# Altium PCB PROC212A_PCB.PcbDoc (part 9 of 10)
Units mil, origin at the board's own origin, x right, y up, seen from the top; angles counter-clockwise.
Board outline 3032.48 x 3598.78 mil, 4 copper layers (Top Layer, L2_GND1, L3_PWR1, Bottom Layer), stack 60.58 mil thick; 432 components, 310 nets, 7775 pads, 1236 vias.
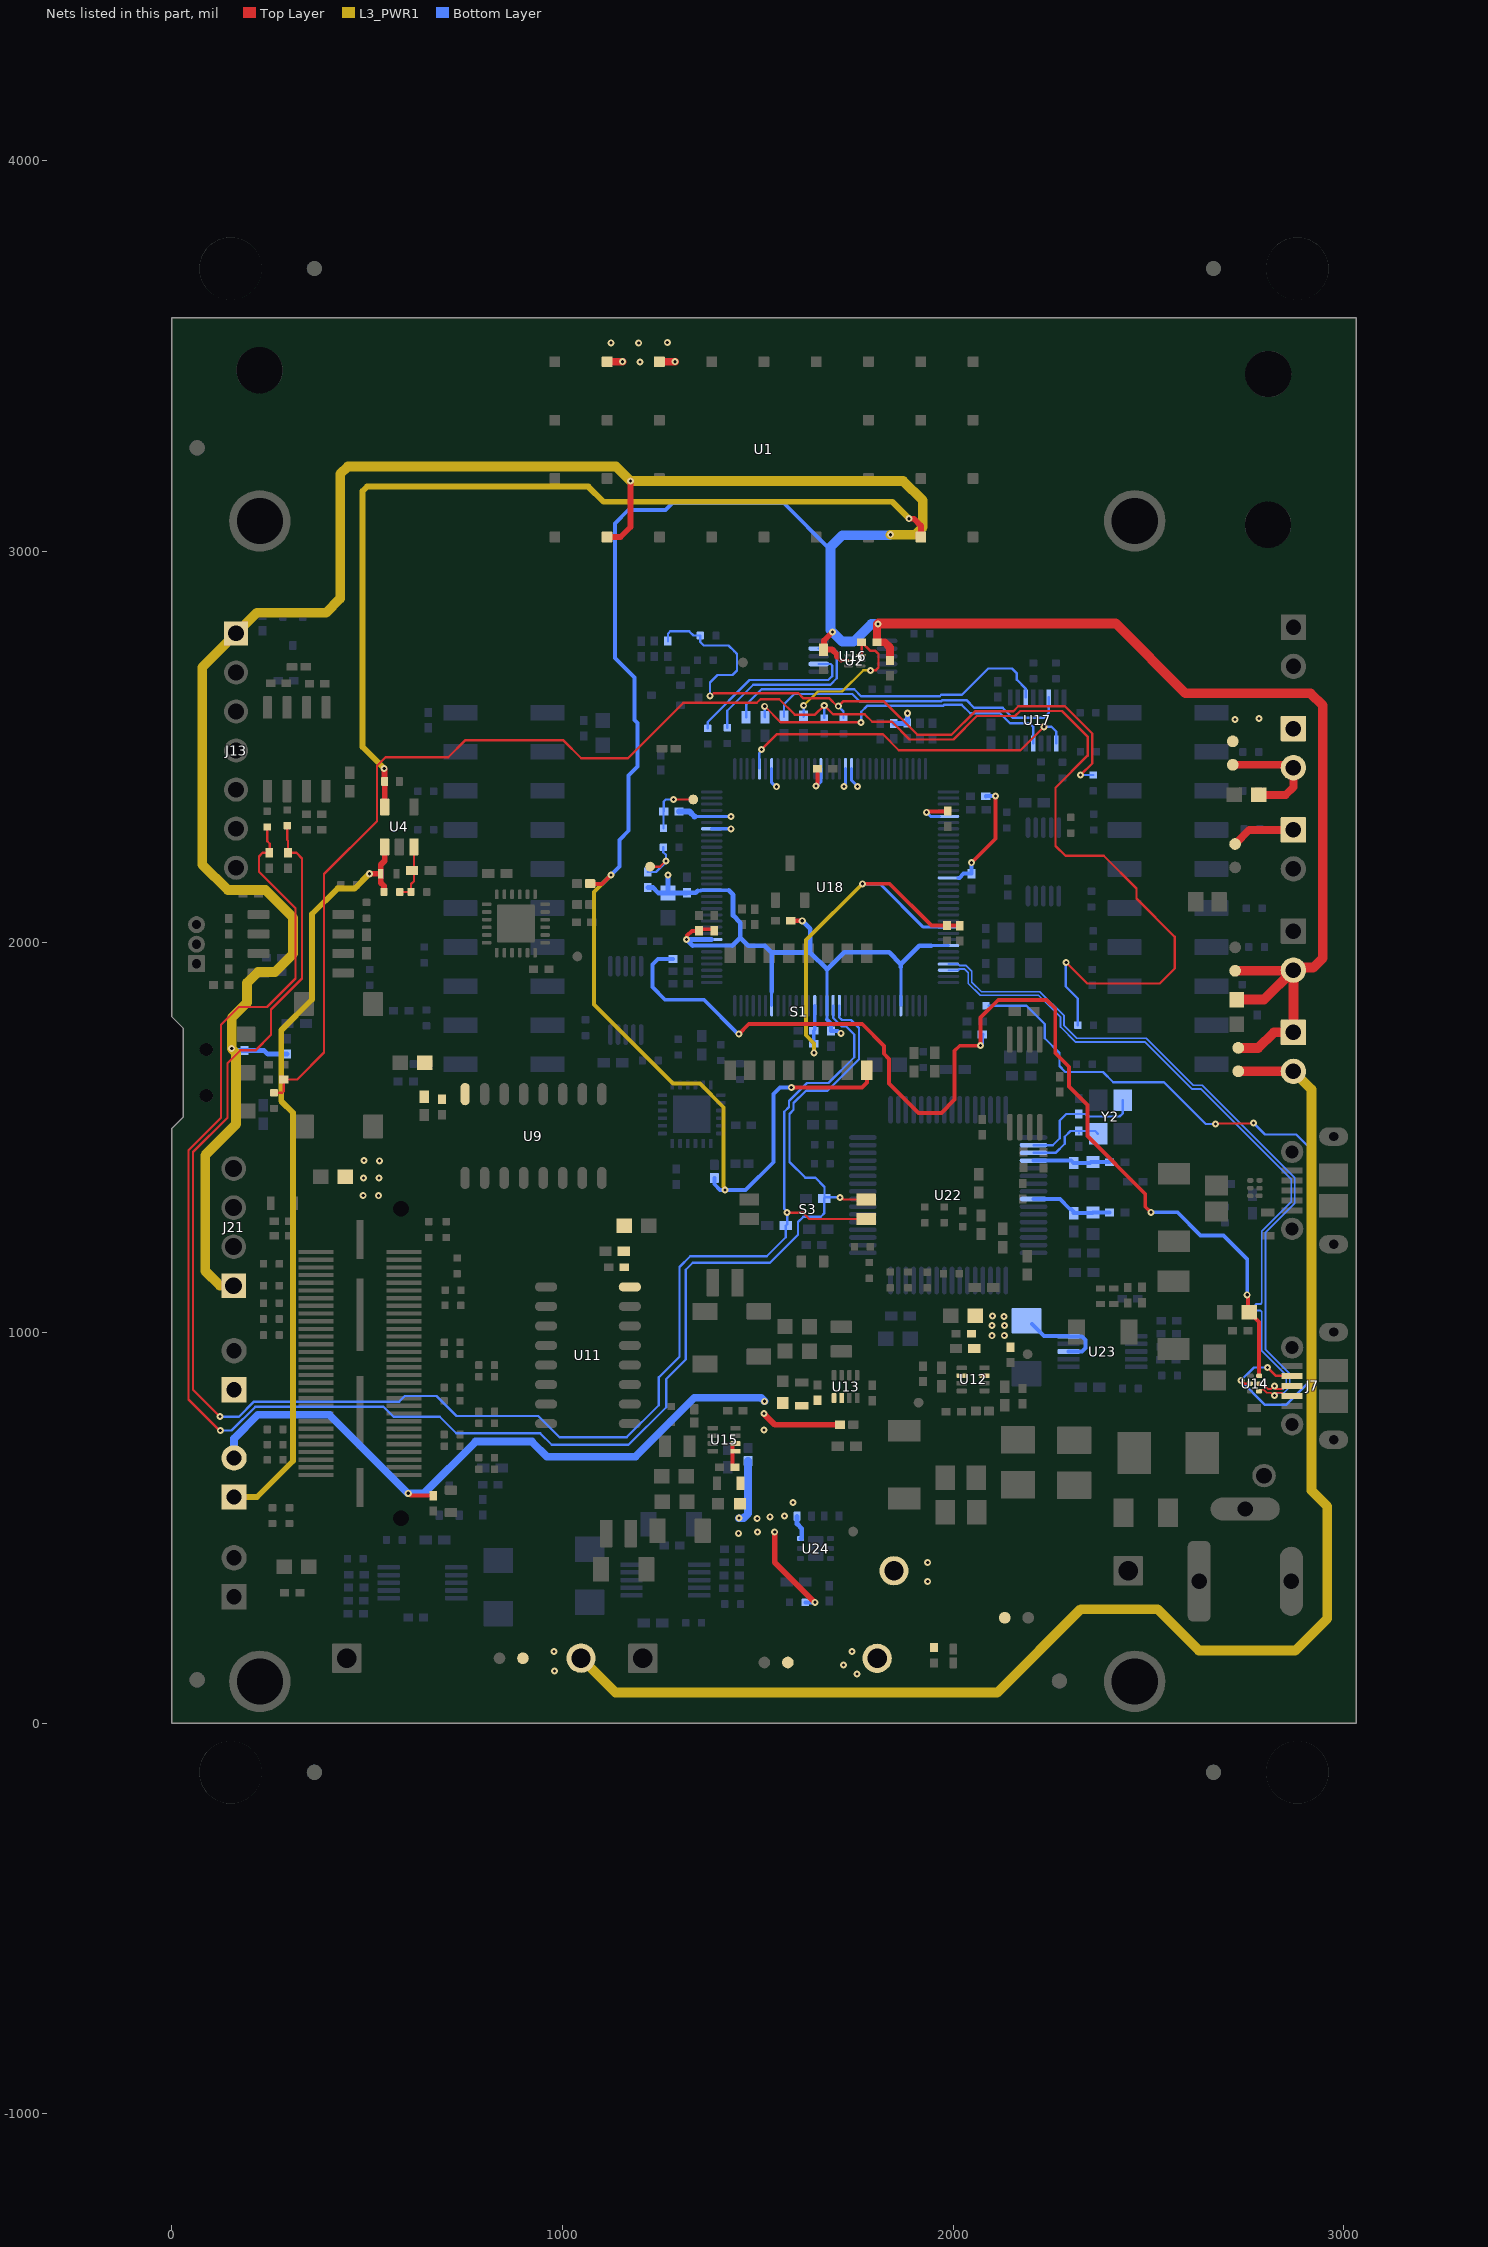
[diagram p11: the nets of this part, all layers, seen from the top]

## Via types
v1: diameter 18, hole 8, Top Layer to Bottom Layer, tented both sides, 1224 vias
v2: diameter 19.68, hole 7.87, Top Layer to Bottom Layer, tented both sides, 10 vias
v3: diameter 19.68, hole 7.87, Top Layer to Bottom Layer, 2 vias

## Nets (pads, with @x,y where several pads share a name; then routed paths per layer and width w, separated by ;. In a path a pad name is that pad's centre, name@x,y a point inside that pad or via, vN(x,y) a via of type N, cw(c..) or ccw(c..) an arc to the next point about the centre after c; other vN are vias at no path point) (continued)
VCC_5V: C42.1 C44.1 C45.1 C50.1 C52.1 C54.1 C93.2 J9.2 J23.2 R79.1 R88.2 R91.2 R93.2 R200.1 R217.2 U13.1 U13.2 U15.1 U15.2 U24.6 | length 2455.6
  Top Layer w10: v1(605.04,588.74) 611.23,582.55 R88.2@668.94,582.55 ; C50.1@1434.81,661.43 U15.2@1434.81,715.37 ; U15.2@1442.31,715.37 U15.2@1443.1,716.16
  Top Layer w15: v1(1515.53,792.55) 1543.71,764.37 R79.1@1710.91,764.37 ; v1(1543.33,489.54) 1543.33,411.62 1645.36,309.6 v1(1646.03,309.6)
  Bottom Layer w10: R217.2@1621.39,309.52 1645.96,309.52 v1(1646.03,309.6)
  Bottom Layer w12: C93.2@1600.57,530.16 1600.57,510.15 1612.31,498.42 1612.31,473.03 1612.21,472.94 U24.6@1609.67,472.94
  Bottom Layer w20: J23.2@158.99,679.14 158.99,728.69 219.9,789.61 403.11,789.61 v1@603.98,588.74 ; v1@605.23,588.92 645.39,588.92 777.56,721.09 921.53,721.09 960.12,682.5 1186.49,682.5 1337.42,833.43 1508.41,833.43 v1(1517.53,824.31) ; v1(1451.96,525.03) 1463.6,525.03 1475.32,536.74 R200.1@1475.31,671.1
  other v1: 1935.1,362.4 1935.1,411.4 1450.85,486.29 1499.07,489.63 1498.51,523.91 1531.17,528.58 1567.91,530.32 1589.93,564.89 1515.93,750.88
VCC_5V_IN: C34.1 C38.1 C39.1 J22.1 R37.1 R65.2 R192.1 U12.2 U12.7 U23.8 U23.10 | length 221.8
  Bottom Layer w10: R192.1@2202.24,1021.97 2233.16,991.04 U23.10@2295.6,991.04 2296.15,990.5 2329.58,990.5 2339.31,980.77 2339.31,960.41 2330.57,951.67 U23.8@2295.6,951.67
  other v1: 2099.57,992.12 2131.18,992.51 2131.57,1018.11 2099.96,1018.69 2100.54,1042.54 2130.02,1041.77 489.7,1351 529.31,1350.65 490.12,1396.41 529.73,1396.06 491.47,1440.37 531.08,1440.01
VCC_IO_3V3: J4.1 J10.2 J20.2 R94.2 | length 3692.2
  Top Layer w25: J4.1@2730.38,1669.05 2871.33,1669.05 J20.2@2871.44,1668.94
  L3_PWR1 w25: R94.2@1047.49,166.61 1135.46,78.63 2113.4,78.63 2326.87,292.09 2523.31,292.09 2629.31,186.09 2876.31,186.09 2958.31,268.09 2958.31,555.09 2917.46,595.94 2917.46,1622.92 J20.2@2871.44,1668.94
  Bottom Layer w20: R94.2@1046.99,166.11 R94.2@1047.49,166.61
  other v1: 979.56,133.91 978.31,184.09
VCC_IO_MODULE: C1.2 C17.1 J3.2 J4.2 J13.1 J18.2 J20.1 J21.1 R1.2 R2.2 R14.2 R165.2 R167.2 R181.2 S1.16 U1.29 U2.5 | length 11366.5
  Top Layer w8: 1713.16,2720.77 U2.5@1732.28,2720.77
  Top Layer w10: R14.2@1070.85,2149.73 1071.69,2148.89 1101.1,2148.89 v1(1124.31,2172.09) ; v1(1585.71,1627.66) 1766.91,1627.66 1779.28,1640.02 S1.16@1779.28,1671.68 ; C1.2@1668.49,2748.77 C1.2@1669.58,2749.87 ; 1702.87,2731.07 1713.16,2720.77 ; v1@1805.32,2809.62 1807.78,2812.09 v1(1807.78,2814.25)
  Top Layer w15: U1.29@1114.16,3037.2 1148.41,3037.2 1173.93,3062.72 v1(1173.93,3180.67) ; C1.2@1668.49,2748.77 1690.4,2748.77 1702.87,2736.3 1702.87,2731.07 ; C1.2@1669.58,2749.87 1669.58,2772.37 v1(1691.31,2794.09)
  Top Layer w20: R1.2@1805.21,2767.81 1825.06,2767.81 1838.44,2754.43 R2.2@1838.44,2721.1 ; R1.2@1805.32,2767.91 v1@1805.32,2809.62
  Top Layer w25: v1(1807.78,2814.25) 1809.15,2815.63 2416.73,2815.63 2595.43,2636.93 2915.39,2636.93 2946.61,2605.72 2946.61,1959.39 2922.31,1935.09 2878.37,1935.09 J18.2@2871.42,1928.15 ; J3.2@2722.11,1926.39 J18.2@2869.67,1926.39 ; C17.1@2726.37,1852.72 2796,1852.72 J18.2@2869.67,1926.39 ; J4.2@2730.38,1729.05 2781.27,1729.05 2821.15,1768.94 J20.1@2871.44,1768.94 J18.2@2871.42,1928.15 ; J18.2@2869.67,1926.39 J18.2@2871.42,1928.15
  L3_PWR1 w10: v1(1124.31,2172.09) 1080.31,2128.09 1080.31,1840.09 1282.84,1637.56 1351.84,1637.56 1412.31,1577.1 1412.31,1374.14 1414.31,1372.14 1414.31,1366.48 v1(1415.84,1364.95)
  L3_PWR1 w25: J21.1@158.04,1120.16 123.13,1120.16 85.22,1158.07 85.22,1454.52 164.32,1533.62 164.32,1715.87 v1(153.02,1727.17) 153.04,1805.89 192.02,1844.86 192.02,1895.65 220,1923.64 264.05,1923.64 310.27,1969.86 310.27,2062.44 239.62,2133.08 143.05,2133.08 77.3,2198.84 77.3,2703.53 J13.1@164.16,2790.39 216.87,2843.09 394.31,2843.09 430.72,2879.51 430.72,3198.46 450.23,3217.98 1136.63,3217.98 v1(1173.93,3180.67) 1872.34,3180.67 1922.59,3130.43 1922.59,3062.1 1903.58,3043.09 v1(1839.31,3043.09)
  Bottom Layer w10: v1(1124.31,2172.09) 1145.51,2193.3 1145.51,2261.3 1169.31,2285.09 1169.31,2426.09 1192.49,2449.28 1192.49,2560.91 1184.31,2569.09 1184.31,2677.09 1134.31,2727.09 1134.31,3072.09 1168.23,3106.02 1263.37,3106.02 1281.2,3123.85 1566.55,3123.85 1686.31,3004.09 ; R181.2@1388.79,1396.21 1388.79,1379.86 1403.7,1364.95 v1(1415.84,1364.95) ; v1@1416.05,1364.74 1468.7,1364.74 1540.16,1436.2 1540.16,1611.47 1556.57,1627.87 1585.5,1627.87 v1(1585.71,1627.66) ; v1@1838.01,3041.8 v1(1839.31,3043.09)
  Bottom Layer w12: v1@159.56,1722.26 181.89,1722.26 182,1722.36 R165.2@185.74,1722.36 235.93,1722.36 245.03,1713.26 R167.2@295.22,1713.26
  Bottom Layer w25: 1686.31,3004.09 1686.31,2799.09 1715.96,2769.44 1745.94,2769.44 1790.75,2814.25 v1(1807.78,2814.25) ; 1686.31,3011.69 1716.41,3041.8 v1@1838.01,3041.8
VCC_MOD_3V3: J1.1 J11.2 J16.1 R95.2 | length 6.4
  Bottom Layer w12: R95.2@1801.04,161.56 R95.2@1805.59,166.11
  other v1: 1753.58,125.7 1719.08,149.01 1741.18,183.5 2721.42,2570.21 2782.91,2572.3
VCC_MODULE: C5.1 J1.2 J2.2 J16.2 J17.1 U1.7 U1.8 | length 545.4
  Top Layer w20: U1.8@1110.93,3486.02 v1(1154.07,3486.02) ; U1.7@1244.78,3486.02 v1(1287.93,3486.02) ; J1.2@2716.19,2453.87 2864.13,2453.87 J16.2@2871.42,2446.58 ; J2.2@2722.11,2251.14 2758.33,2287.36 J17.1@2871.42,2287.36 ; C5.1@2782.96,2376.89 2851.55,2376.89 2871.42,2396.76 J16.2@2871.42,2436.58
  other v1: 1198.41,3485.13 1123.9,3534.4 1195.09,3534.23 1268.22,3535.26
VCC_XDS_3V3: C3.1 C11.1 C12.2 C63.2 C64.2 C70.1 R5.2 R22.2 R119.2 R122.2 R135.1 R136.2 R143.1 R145.2 U18.7 U18.8 U18.16 U18.26 U18.28 U18.39 U18.47 U18.51 U18.52 U18.69 U18.79 U18.90 U18.101 U18.113 U18.122 | length 2739.4
  Top Layer w10: v1(1317.29,2006.8) 1318.82,2008.33 1318.82,2016.59 1331.11,2028.88 1345.5,2028.88 1349.45,2032.82 1387.03,2032.82 C11.1@1387.18,2032.67 ; v1@1613.69,2054.43 v1(1613.84,2054.57) ; v1(1649.14,2399.46) 1649.14,2401.63 1652.73,2405.21 C3.1@1652.73,2443.69 ; v1(1931.89,2332.35) 1933.42,2333.88 1984.69,2333.88 R5.2@1986.29,2335.49 ; v1(2046.99,2203.22) 2108.37,2264.6 v1(2108.37,2374.15)
  Top Layer w12: R22.2@1584.59,2054.43 v1@1613.69,2054.43
  Bottom Layer w8: 1337.93,2321.64 U18.28@1381.98,2321.64 v1@1431.21,2321.64 ; U18.26@1381.98,2290.14 v1@1431.21,2290.14 ; U18.122@1535.52,1837.39 1535.52,1872.69 ; U18.39@1535.52,2443.69 1535.52,2408.39 1546.08,2397.83 v1(1547.57,2397.83) ; v1(1649.14,2399.46) 1650.96,2399.46 1661.51,2410.01 U18.47@1661.51,2443.69 ; 1677.26,1801.72 U18.113@1677.26,1837.39 1677.26,1929.89 ; v1(1721.05,2398.37) 1721.05,2401.08 1724.5,2404.52 U18.51@1724.5,2443.69 ; U18.52@1740.25,2443.69 1740.25,2413.63 1755.31,2398.57 v1(1755.48,2398.57) ; U18.101@1866.23,1837.39 1866.23,1936.26 ; v1(1931.89,2332.35) 1942.6,2321.64 U18.69@1964.72,2321.64 ; 1944.5,1990.93 U18.90@1988.28,1990.93
  Bottom Layer w10: 1333.16,1990.93 U18.7@1381.98,1990.93 1434.89,1990.93 ; 1346.21,2131.41 1352.98,2131.41 1354.23,2132.66 1425.42,2132.66 ; 1677.26,1801.72 1687.52,1791.46 C70.1@1687.52,1772.66 1704.58,1772.66 1710.73,1766.51 v1(1712.89,1766.51) ; U18.79@2014.21,2164.41 2016.12,2164.41 2026.89,2175.19 C63.2@2047.17,2175.19 v1@2047.17,2203.04 ; R135.1@2083.66,2373.28 2084.1,2373.72 2107.94,2373.72 v1(2108.37,2374.15)
  Bottom Layer w12: R143.1@1218.51,2139.89 1231.53,2139.89 1245.8,2125.62 R145.2@1270.05,2125.62 ; v1(1270.41,2171.97) 1270.05,2171.62 R145.2@1270.05,2125.62 ; v1(1317.29,2006.8) v1@1317.41,2006.68 ; 1333.16,1990.93 v1@1317.41,2006.68 ; 1346.21,2131.41 1341.36,2126.55 C64.2@1318.67,2126.55 1317.74,2125.62 R145.2@1270.05,2125.62 ; U18.8@1381.98,2006.68 v1@1317.41,2006.68 ; 1425.42,2132.66 1436.65,2121.44 1436.65,2068.3 1455.39,2049.55 1455.39,2011.44 ; v1@1431.21,2290.14 v1(1431.3,2290.05) ; 1434.89,1990.93 1455.39,2011.44 ; 1535.52,1872.7 1536.09,1873.27 1536.09,1973.16 ; v1(1613.84,2054.57) 1633.99,2034.42 1633.99,1973.16 ; R122.2@1848.12,2559.82 R119.2@1882.2,2559.82 ; 1866.23,1936.26 1866.23,1943.73 ; R119.2@1882.99,2560.61 1883.25,2560.86 1883.25,2585.66 v1(1883.51,2585.92) ; 1944.5,1990.93 1913.44,1990.93 1866.23,1943.73 ; 1455.39,2011.44 1475.9,1990.93 1518.31,1990.93 1536.09,1973.16 ; 1536.09,1973.16 1633.99,1973.16 ; 1633.99,1973.16 1677.26,1929.89 1721.23,1973.86 1836.1,1973.86 1866.23,1943.73
  Bottom Layer w15: R136.2@1298.63,2334.04 1325.54,2334.04 1337.93,2321.64
  other v1: 1431.3,2321.55
VDD1_3V3: C25.1 C26.1 R43.2 U11.16
VDD2_3V3: C19.1 C20.1 R28.2 U9.16
VDDC_1: C13.2 C14.2 C71.2 C73.1 U18.87 U18.115 | length 1183.8
  Top Layer w10: v1(1767.75,2149.32) 1837.55,2149.32 1944.43,2042.43 C13.2@1984.32,2042.43 1984.64,2042.11 C14.2@2017.02,2042.11
  L3_PWR1 w10: v1(1644.37,1716.59) 1644.37,1740.52 1623.45,1761.44 1623.45,2005.02 v1(1767.75,2149.32)
  Bottom Layer w8: v1(1644.37,1716.59) 1644.37,1738.52 C73.1@1643.19,1739.69 C71.2@1643.19,1773.19 1645.76,1775.76 U18.115@1645.76,1837.39 ; v1(1767.75,2149.32) 1812.74,2149.32 1923.88,2038.18 U18.87@1988.28,2038.18
VPHY_FTDI: C83.2 C84.1 L8.2 U22.4 | length 194.4
  Bottom Layer w10: U22.4@2206.05,1440.63 2287.46,1440.63 2302.46,1440.63 C83.2@2308.76,1434.33 C84.1@2350.85,1434.33 ; C84.1@2353.23,1436.71 L8.2@2400.22,1436.71
VPLL_FTDI: C86.2 C87.1 L10.2 U22.9 | length 209.6
  Bottom Layer w10: U22.9@2206.05,1342.2 2273.33,1342.2 2298.69,1316.84 2301.95,1316.84 2308.76,1310.03 C86.2@2308.76,1306.77 ; C86.2@2308.76,1306.09 C87.1@2356.58,1306.09 ; C87.1@2358.23,1307.74 L10.2@2400.71,1307.74
VPP_1P7: C4.2 U1.23 U4.5 | length 2336
  Top Layer w10: C4.2@544.55,2411.67 C4.2@544.73,2411.48
  Top Layer w15: v1(543.5,2444.52) 543.5,2443.71 544.55,2442.66 C4.2@544.55,2411.67 ; U4.5@544.73,2346.09 C4.2@544.73,2411.48 ; v1(1887.47,3083.97) 1899.91,3083.97 1917.55,3066.34 1917.55,3043.48 1917.97,3043.06 U1.23@1917.97,3037.86
  L3_PWR1 w15: v1(543.5,2444.52) 488.31,2499.72 488.31,3155.07 499.3,3166.06 1066.26,3166.06 1105.04,3127.28 1844.37,3127.28 v1@1887.47,3084.17
VPP_LDO_EN: R13.2 R16.2 R17.1 U4.3 | length 147.6
  Top Layer w5.9: R17.1@583.21,2128.25 612.08,2128.25 R16.2@612.23,2128.4 612.23,2148.4 619.77,2155.93 619.77,2183.31 619.53,2183.54 U4.3@619.53,2243.72
VPP_LDO_IN_5V: C7.1 J23.1 R17.2 U4.1 | length 1975.4
  Top Layer w15: v1(505.6,2175) 505.72,2175.11 C7.1@534.73,2175.11 ; R17.2@542.85,2128.25 542.85,2143.86 534.73,2151.98 C7.1@534.73,2175.11 ; U4.1@544.73,2243.72 544.73,2208.23 534.73,2198.23 C7.1@534.73,2175.11
  L3_PWR1 w15: J23.1@158.99,579.15 217.58,579.15 309.86,671.42 309.86,1562.9 279.98,1592.78 279.98,1774.49 358.71,1853.23 358.71,2071.68 423.18,2136.15 ; 423.18,2137.44 467.78,2137.44 v1@505.34,2175
XDS_MCU_SOP0: R31.1 R32.2 R118.1 R163.1 | length 4360.4
  Top Layer w5.9: R32.2@261.32,1614.52 282.22,1614.52 286.08,1618.38 R31.1@286.08,1648.29 320.91,1648.29 389.57,1716.95 389.57,2174.41 524.82,2309.66 524.82,2451.23 546.69,2473.09 707.34,2473.09 750.69,2516.44 1002.35,2516.44 1047.97,2470.83 1167.78,2470.83 1309.49,2612.54 1497.57,2612.54 1506.99,2621.97 1554.85,2621.97 1594.42,2582.4 1646.54,2582.4 v1(1670.19,2606.04) 1692.68,2583.55 1773.51,2583.55 1792.97,2564.09 1843.31,2564.09 1888.49,2518.91 2000.95,2518.91 2060.83,2578.78 2158.86,2578.78 2171.96,2591.88 2278.74,2591.88 2344.45,2526.18 2344.45,2477.43 2262.48,2395.45 2262.48,2246.35 2287.69,2221.13 2385.72,2221.13 2469.73,2137.12 2469.73,2111.35 2567.74,2013.34 2567.74,1932.33 2529.21,1893.8 2343.48,1893.8 v1(2289.63,1947.66)
  Bottom Layer w5.9: R118.1@1669.81,2573.69 1669.81,2605.67 v1(1670.19,2606.04) ; v1(2289.63,1947.66) 2288.77,1946.8 2288.77,1886.12 2319.35,1855.54 R163.1@2319.35,1787.22
XDS_MCU_SOP1: R98.2 R100.1 R117.1 R132.1 | length 1672.2
  Top Layer w5.9: v1(1377.62,2630.66) 1380.59,2630.66 1387.12,2637.19 1604.12,2637.19 1617.32,2623.99 1683.58,2623.99 1703.62,2603.96 v1(1706.07,2603.96) 1718.44,2616.32 1823.08,2616.32 1908.59,2530.81 1996.02,2530.81 2055.9,2590.68 2153.93,2590.68 2167.03,2603.78 2286.62,2603.78 2356.35,2534.05 2356.35,2457.45 v1(2326.4,2427.5)
  Bottom Layer w5.9: R100.1@1269.86,2770.59 1269.86,2789.57 1276.1,2795.82 1324.17,2795.82 1335.04,2784.94 R98.2@1352.58,2784.94 1352.58,2768.6 1361.7,2759.48 1425.14,2759.48 1440.01,2744.61 1446.9,2737.76 1446.9,2695.18 1435.39,2683.67 1396.82,2683.67 1377.62,2664.47 v1(1377.62,2630.66) ; v1(1706.07,2603.96) 1719.52,2590.5 R117.1@1719.52,2574.08 ; v1(2326.4,2427.5) 2326.47,2427.57 R132.1@2358.64,2427.57
XDS_NRST: R1.1 R112.2 U2.3 | length 384.5
  Top Layer w5.9: U2.3@1763.78,2734.55 1765.84,2736.61 R1.1@1765.84,2767.81 1787.4,2746.25 1800.21,2746.25 1808.96,2737.51 1808.96,2702.93 1801.69,2695.67 v1(1788.59,2695.67)
  L3_PWR1 w5.9: v1@1617.92,2605.61 1653.89,2641.58 1715.78,2641.58 1769.86,2695.67 v1(1788.59,2695.67)
  Bottom Layer w5.9: R112.2@1616.86,2577.13 1617.57,2577.84 v1(1617.57,2605.61)
XDS_SCL: R6.2 R12.2 R186.2 S3.3 U18.112 | length 4553.9
  Top Layer w5.9: v1(123.46,784.97) 122.82,784.97 54.13,853.65 54.13,1462.31 142.21,1550.4 142.21,1689.8 175.14,1722.72 213.66,1722.72 253.54,1762.6 253.54,1827.2 333.19,1906.85 333.19,2214.28 318.97,2228.5 R12.2@297.37,2228.5 297.37,2259.56 295.02,2261.91 R6.2@295.02,2298.07 ; v1(1575.18,1307.58) 1576.02,1306.73 1616.02,1306.73 1631.88,1290.87 S3.3@1778.09,1290.87
  Bottom Layer w5.9: v1(123.46,784.97) 171.55,784.97 210.02,823.44 581.84,823.44 596.02,837.63 677.53,837.63 728.51,786.65 938.06,786.65 992.52,732.19 1164.19,732.19 1246.41,814.4 1246.41,885.44 1299.34,938.38 1299.34,1167.85 1326.85,1195.35 1522.78,1195.35 1571.73,1244.3 R186.2@1571.73,1274.3 1575.18,1277.74 v1(1575.18,1307.58) 1575.18,1310.35 1567.97,1317.56 1567.97,1565.84 1579.76,1577.62 1579.76,1592.79 1625.97,1639.01 1681.3,1639.01 1747.15,1704.86 1747.15,1763.36 1726.05,1784.46 1714.47,1784.46 1693,1805.92 U18.112@1693,1837.39
XDS_SDA: R7.2 R11.2 R184.2 S3.4 U18.111 | length 4684
  Top Layer w5.9: v1(123.78,749.42) 121.53,749.42 42.23,828.72 42.23,1467.24 125.4,1550.42 125.4,1788.21 171.04,1833.85 243.36,1833.85 316.38,1906.87 316.38,2086.8 222.84,2180.34 222.84,2219.33 232,2228.5 R11.2@249.33,2228.5 250.25,2229.42 250.25,2252.05 243.74,2258.56 R7.2@243.74,2294.72 ; v1(1710.64,1346.34) 1713.91,1346.34 1719.38,1340.87 S3.4@1778.09,1340.87
  Bottom Layer w5.9: v1(123.78,749.42) 152.83,749.42 213.64,810.22 541.75,810.22 567.23,784.74 685.79,784.74 728.18,742.35 942.71,742.35 972.25,712.81 1169.08,712.81 1265.48,809.22 1265.48,881.27 1315.79,931.57 1315.79,1161.03 1333.66,1178.91 1531.18,1178.91 1602.8,1250.53 1602.8,1283.09 1616.69,1296.98 1661.14,1296.98 1670.51,1306.34 R184.2@1670.51,1343.83 ; R184.2@1670.95,1345.18 1670.95,1373.2 1647.17,1396.97 1621.4,1396.97 1581.19,1437.18 1581.19,1560.19 1591.66,1570.66 1591.66,1587.86 1623.33,1619.54 1678.65,1619.54 1759.21,1700.09 1759.21,1779.89 1738.63,1800.47 1715.29,1800.47 1708.75,1807.01 U18.111@1708.75,1837.39 ; R184.2@1672.11,1346.34 v1(1710.64,1346.34)
XDS_TCK: R115.2 U17.3 | length 854.1
  Bottom Layer w5.9: R115.2@1470.11,2575.82 1470.11,2607.79 1509.49,2647.18 1746.88,2647.18 1764.94,2629.12 1965.75,2629.12 1969.89,2633.26 2022.73,2633.26 2089.85,2700.38 2150.8,2700.38 2163.39,2687.79 2163.39,2671.79 2185.7,2649.48 U17.3@2185.7,2626.66
XDS_TDI: R113.2 U17.6 | length 793.5
  Bottom Layer w5.9: R113.2@1566.92,2576.83 1566.92,2608.8 1593.4,2635.28 1741.95,2635.28 1760.59,2616.64 1970.11,2616.64 1973.05,2619.59 2034.03,2619.59 2053.99,2599.63 2127.45,2599.63 2152.47,2574.61 2232.98,2574.61 2244.75,2586.39 U17.6@2244.75,2626.66
XDS_TDO: U17.10 U18.37 | length 899.4
  Top Layer w5.9: v1(1509.82,2492.86) 1549.47,2532.51 1819.89,2532.51 1861.05,2491.35 2172.83,2491.35 v1(2232.8,2551.32)
  Bottom Layer w5.9: U18.37@1504.03,2444.32 1504.03,2483.82 1509.82,2489.62 v1(1509.82,2492.86) ; v1(2232.8,2551.32) 2233.21,2551.73 2251.52,2551.73 2264.27,2538.97 U17.10@2264.27,2508.72
XDS_TMS: R114.2 U17.13 | length 833.2
  Top Layer w5.9: v1(1517.7,2603.7) 1558.89,2562.51 v1(1764.63,2562.51)
  Bottom Layer w5.9: v1(1517.7,2603.7) 1517.7,2576.32 R114.2@1518.21,2575.82 ; v1(1764.63,2562.51) 1764.63,2589.87 1779.51,2604.74 1975.04,2604.74 1977.67,2607.38 2022.37,2607.38 2044.01,2585.74 2119.96,2585.74 2145.53,2560.16 2196.21,2560.16 2205.38,2550.99 U17.13@2205.38,2508.55
XDS_UART_RX: R136.1 R139.2 TP2.1 | length 146.4
  Top Layer w5.9: v1(1284.31,2365.09) TP2.1@1334.73,2365.09
  Bottom Layer w5.9: R139.2@1258.78,2291.52 1258.78,2333.84 R136.1@1259.12,2334.18 1259.12,2360.01 1264.2,2365.09 v1(1284.31,2365.09)
XDS_UART_TX: R142.2 R143.2 TP3.1 | length 144.4
  Top Layer w5.9: TP3.1@1224.1,2193.24 1250.18,2193.24 v1(1264.85,2207.91)
  Bottom Layer w5.9: R143.2@1218.51,2179.26 1239.2,2179.26 1264.85,2204.91 v1(1264.85,2207.91) 1264.85,2223.48 1258.12,2230.22 R142.2@1258.12,2242.72
XDS_UARTB_RS232_RX: R124.2 U16.4 | length 476.3
  Bottom Layer w5.9: R124.2@1422.04,2548.68 1422.04,2592.53 1488.58,2659.08 1685.99,2659.08 1702.37,2675.45 1702.37,2743.5 1694.4,2751.47 U16.4@1655.91,2751.47
XDS_UARTB_RS232_TX: R125.2 U16.2 | length 447.1
  Bottom Layer w5.9: R125.2@1371.68,2547.32 1371.68,2563.63 1479.03,2670.98 1680.42,2670.98 1690.47,2681.02 1690.47,2708.19 1686.56,2712.1 U16.2@1655.91,2712.1
XDSET_1_DM: J7.2 U14.4 U18.93 | length 1886.3
  Top Layer w4.5: U14.4@2783.63,849.81 2786.52,849.81 2790.83,854.12 2795.61,854.12 2803.29,846.44 2813.77,846.44 2821.27,838.94 v1(2823.16,838.94) 2823.16,843.75 2825.85,846.44 2841.14,846.44 J7.2@2843.77,843.8 ; J7.2@2843.77,843.77 2849.4,838.14 J7.2@2868.1,838.14
  Bottom Layer w4.5: U18.93@1988.28,1943.69 2012.82,1943.69 2016.19,1940.31 2032.63,1940.31 2048.06,1924.88 2048.06,1897.6 2072.82,1872.84 2222.34,1872.84 2284.22,1810.97 2284.22,1786.26 2316.98,1753.49 2494.45,1753.49 2614.8,1633.15 2638.19,1633.15 2874.82,1396.51 2874.82,1331.17 2799.62,1255.97 2799.62,1044.75 2799.62,957.78 2862.31,895.09 2862.31,861.37 2847.38,846.44 2832.54,846.44 2825.04,838.94 v1(2823.16,838.94)
XDSET_1_DP: J7.3 U14.5 U18.94 | length 1885.6
  Top Layer w4.5: U14.5@2783.63,869.49 2785.88,869.49 2792.25,863.12 2799.34,863.12 2807.02,855.44 2813.77,855.44 2821.27,862.94 v1(2823.16,862.94) 2823.16,858.13 2825.85,855.44 2841.14,855.44 2843.77,858.08 2849.4,863.74 J7.3@2868.1,863.74
  Bottom Layer w4.5: U18.94@1988.28,1927.94 2012.82,1927.94 2016.19,1931.31 2028.9,1931.31 2039.06,1921.15 2039.06,1908.73 2039.06,1893.87 2069.09,1863.84 2218.61,1863.84 2275.22,1807.24 2275.22,1782.53 2313.26,1744.49 2490.72,1744.49 2611.07,1624.15 2634.46,1624.15 2865.82,1392.78 2865.82,1334.9 2790.62,1259.7 2790.62,1095.25 2790.62,1076.5 2787.32,1073.2 2775.92,1073.2 2772.62,1069.9 2772.62,1060 2775.92,1056.7 2787.32,1056.7 2790.62,1053.4 2790.62,1044.75 2790.62,954.05 2853.31,891.37 2853.31,865.09 2843.65,855.44 2832.54,855.44 2825.04,862.94 v1(2823.16,862.94)
XDSET_1_ID: J7.4 R160.1 U14.2 | length 2019.2
  Top Layer w5.9: v1(2671.87,1534.37) 2673.1,1535.6 2767.95,1535.6 v1(2769.17,1536.83) ; v1(2736.73,877.27) 2737.45,877.27 2745.22,869.49 U14.2@2760.01,869.49 ; v1(2805.36,910.84) 2826.88,889.33 J7.4@2868.1,889.33
  Bottom Layer w5.9: R160.1@2091.04,1836.89 2188.24,1836.89 2234.92,1790.21 2234.92,1753.78 2272.4,1716.3 2272.4,1682.44 2287.37,1667.47 2383.73,1667.47 2409.85,1641.35 2540.2,1641.35 2647.18,1534.37 v1(2671.87,1534.37) ; v1(2769.17,1536.83) 2798.84,1507.16 2878.64,1507.16 2911.08,1474.72 2911.08,873.86 2852.31,815.09 2798.9,815.09 v1(2736.73,877.27) 2770.31,910.84 v1(2805.36,910.84)
XDSET_1_VBUS: R60.1 R153.2 R166.2 U14.6 | length 2848.5
  Top Layer w10: v1(1451.39,1764.73) 1476.75,1790.09 1767.45,1790.09 1823.41,1734.13 1823.41,1714.17 1836.41,1701.18 1836.41,1637.75 1911.46,1562.7 1969.97,1562.7 2004.15,1596.88 2004.15,1721.67 2017.13,1734.65 v1@2070.09,1734.65 ; v1@2070.31,1735.49 2070.31,1806.78 2115.62,1852.09 2239.18,1852.09 2261.69,1829.58 2261.69,1715.92 2296.68,1680.93 2296.68,1630.51 2344.49,1582.7 2344.49,1503.07 2492.07,1355.5 2492.07,1322.42 v1(2506.29,1308.19) ; v1(2753.09,1096.99) 2754.82,1095.25 2754.82,1055.7 R60.1@2758.12,1052.4 2783.63,1026.89 U14.6@2783.63,889.18
  Bottom Layer w10: R153.2@1283.04,1956.64 1244.31,1956.64 1229.97,1942.3 1229.97,1884.93 1262.62,1852.27 1361.79,1852.27 1449.33,1764.73 v1(1451.39,1764.73) ; v1@2074.42,1741.14 2074.42,1762.72 R166.2@2074.93,1763.23 ; v1(2506.29,1308.19) 2575.06,1308.19 2634,1249.25 2692.73,1249.25 2753.09,1188.9 v1(2753.09,1096.99)
  other v1: 2070.63,1735.18
XI_FTDI: C79.1 U22.2 Y2.1 | length 328.3
  Bottom Layer w5.9: U22.2@2206.05,1480 2255.18,1480 2273,1497.81 2273,1543.42 2289.61,1560.04 C79.1@2321.57,1560.04 2338.26,1560.04 2340.51,1557.79 2344.87,1553.43 2350.1,1553.43 ; 2350.1,1553.36 2426.27,1553.36 2434.18,1561.26 Y2.1@2434.18,1595.56
XO_FTDI: C82.1 U22.3 Y2.3 | length 202
  Bottom Layer w5.9: U22.3@2206.05,1460.31 2262.18,1460.31 2285.71,1483.84 2285.71,1501.56 2300.5,1516.35 C82.1@2321.74,1516.35 2363.78,1516.35 Y2.3@2371.19,1508.94 ; C82.1@2322.2,1510.62 C82.1@2322.34,1510.48
pads on no net: FID1.1 FID2.1 FID2_1.1 FID2_1_1.1 FID2_1_2.1 FID2_1_3.1 FID3.1 FID5.1 FID5_1.1 FID5_1_1.1 FID5_1_2.1 FID5_1_3.1 FID6.1 FID7.1 J6.14 J6.15 J6.16 J6.17 J6.19 J6.20 J6.21 J6.22 J6.23 J6.25 J6.27 J6.29 J6.31 J6.33 J6.35 J6.37 J6.39 J6.41 J6.43 J6.45 J6.47 J6.49 J6.MH1 J6.MH2 J14.3 J14.6 J14.8 J14.9 J14.10 J14.11 J14.12 J14.14 J14.15 J14.16 J14.18 J14.20 J15.9 J15.10 J15.18 J15.20 LBL1.0 S1.8 S1.9 SW1. SW1._1 U1.26 U3.1 U3.2 U4.4 U5.3 U8.6 U8.7 U9.9 U9.10 U9.11 U11.1 U11.2 U11.3 U18.2 U18.3 U18.4 U18.5 U18.6 U18.11 U18.12 U18.13 U18.14 U18.15 U18.18 U18.19 U18.20 U18.21 U18.22 U18.23 U18.27 U18.29 U18.30 U18.31 U18.32 U18.41 U18.44 U18.45 U18.46 U18.49 U18.50 U18.53 U18.54 U18.56 U18.57 U18.65 U18.67 U18.71 U18.72 U18.73 U18.74 U18.75 U18.76 U18.77 U18.78 U18.81 U18.82 U18.83 U18.84 U18.85 U18.86 U18.91 U18.92 U18.97 U18.98 U18.99 U18.100 U18.102 U18.103 U18.104 U18.105 U18.106 U18.107 U18.108 U18.109 U18.110 U18.116 U18.117 U18.118 U18.119 U18.120 U18.121 U18.123 U18.124 U18.125 U18.126 U18.127 U18.128 U22.29 U22.30 U22.33 U22.38 U22.39 U22.40 U22.41 U22.43 U22.44 U22.46 U22.53 U22.57 U22.58 U22.59 U22.60 U24.2 U24.5 U24.7_1 U24.7_2

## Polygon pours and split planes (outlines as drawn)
GND on Top Layer "GND_L01_P45266" (solid, remove dead copper, pour order 45266): 3030.48,3599.79 3030.48,0 -3.01,0 -3.01,3599.79
USB_5V on Top Layer "BOTTOM_LAYER_NONET_P-001" (solid, pour order 45265): 2701.31,904.84 2701.31,847.09 2726.31,822.09 2894.67,822.09 2894.67,803.09 2843.31,803.09 2825.31,785.09 2672.31,785.09 2630.14,827.26 2630.14,904.84
VCC_5V on Top Layer "Top Layer-VCC_5V" (solid, remove dead copper, pour order 45240): 1430.47,722.26 1488.12,722.26 1493.68,727.82 1493.68,744.79 1485.12,753.2 1485.12,830.05 1492.94,837.87 1503.6,837.79 1677.91,837.79 1683.99,843.87 1720.62,843.87 1720.62,792.89 1712.42,784.69 1684.1,784.69 1630.26,730.84 1630.26,474.05 1428.31,474.05 1428.31,720.09
GND on Top Layer "Top Layer-GND 2" (solid, remove dead copper, pour order 44926): 1701.87,876.85 1708.44,870.28 1775.68,870.28 1783.16,877.76 1787.32,877.76 1871.07,961.5 1871.07,1034.24 1913.54,1076.72 1964.26,1076.72 1974.76,1076.73 2039.55,1141.52 2069.24,1141.52 2073.83,1136.93 2073.83,1092.31 2060.05,1078.53 2026.75,1078.53 2019.85,1071.63 2020.05,1071.42 2020.05,942.36 2037.14,925.27 2037.14,899.09 1893.26,899.09 1846.48,852.31 1784.62,852.31 1783.4,853.54 1444.65,853.54 1444.71,853.48 1444.71,852.31 1274.34,852.31 1274.34,973.44 1644.01,973.44 1650.09,967.36 1650.09,927.82 1663.51,914.39 1689.96,914.39 1701.87,902.49
VCC_IO_3V3 on Top Layer "VCC_IO_3V3_L01_P45256" (solid, remove dead copper, pour order 45256): 2840.84,1695.99 2857.94,1713.09 2949.31,1713.09 2970.31,1692.09 2970.31,1597.09 2947.05,1573.84 2651.36,1573.84 2651.36,1695.95 2680.84,1695.95 2680.57,1695.99
VCC_IO_MODULE on Top Layer "VCC_IO_MODULE_L01_P45146" (solid, remove dead copper, pour order 45146): 2826.44,1703.23 2857.31,1734.09 2972.36,1734.09 2972.36,1953.76 2959.03,1967.09 2826.31,1967.09 2812.98,1953.76 2673.64,1953.76 2673.31,1954.09 2631.4,1954.07 2631.4,1703.23
VCC_MOD_3V3 on Top Layer "VCC_MOD_3V3_L01_P45255" (solid, remove dead copper, pour order 45255): 2649.31,2602.09 2920.06,2602.09 2920.56,2601.6 2919.77,2600.82 2919.77,2485.92 2650.48,2485.92 2649.31,2487.09
VCC_MODULE on Top Layer "VCC_MODULE_L01_P45254" (solid, remove dead copper, pour order 45254): 2797.96,2223.75 2803.31,2229.09 2917.45,2229.09 2917.45,2481.07 2650.6,2481.07 2650.58,2481.04 2649.76,2481.01 2649.52,2480.77 2649.52,2423.57 2740.46,2423.57 2763.28,2400.76 2763.28,2331.2 2743.07,2310.99 2649.9,2310.99 2649.9,2231.24 2657.39,2223.75
VCC_1V8 on Top Layer "VCC_1V8_L01_P45253" (solid, remove dead copper, pour order 45253): 2785.27,1959.26 2811.11,1985.09 2920.31,1985.09 2925.14,1989.09 2925.14,2214.57 2915.62,2224.09 2817.31,2224.09 2807.78,2214.57 2661.06,2214.57 2661.06,1964.84 2666.64,1959.26
GND on Top Layer "GND_L01_P45252" (solid, remove dead copper, pour order 45252): 598.38,1655.73 1102.18,1655.73 1197.56,1560.34 1197.56,1042.03 1274.12,965.47 1274.12,634.63 1170.59,531.09 632.67,531.09 530.87,632.89 530.87,1146.21 708.31,1146.21 722.35,1160.25 722.35,1289.61 637.49,1374.46 637.49,1431.41 592.86,1476.04 597.16,1480.34 597.16,1642.43
5V_DC on Top Layer "5V_DC_L01_P45194" (solid, pour order 45194): 2398.52,760.41 2411.22,773.12 2458.46,773.12 2519.53,773.12 2519.53,645.32 2489.41,615.2 2489.41,491.27 2032.82,491.27 2032.82,661.27 2368.88,661.27 2398.52,690.39
REG_1V8 on Top Layer "REG_1V8_L01_P45243" (solid, remove dead copper, pour order 45243): 2641.8,2130.61 2641.8,2056.59 2624.26,2039.04 2554.72,2039.04 2325.3,2268.47 2325.3,2729.09 2439.28,2729.09 2534.34,2634.04 2534.34,2395.92 2639.99,2290.27 2639.99,2130.77
NetD3_2 on Top Layer "NETD3_2_L01_P45196" (solid, pour order 45196): 2694.37,1471.35 2713.78,1451.95 2714.25,1447.8 2714.25,1351.38 2630.66,1351.38 2618.19,1338.91 2524.1,1338.91 2505.59,1357.43 2505.59,1440.03 2536.36,1471.35
VDD2_3V3 on Top Layer "VDD2_3V3_L01_P45147" (solid, remove dead copper, pour order 45147): 619.25,1718.37 766.31,1718.37 766.31,1582.48 761.43,1577.61 619.25,1577.61
GND on Top Layer "GND_L01_P45245" (solid, remove dead copper, pour order 45245): 1059.94,1229.21 1128.55,1229.21 1128.55,1148.77 1059.94,1148.77
GND on Top Layer "GND_L01_P45246" (solid, remove dead copper, pour order 45246): 1514.2,1736.26 1516.36,1734.1 1747.83,1734.1 1747.83,1641.15 1748.44,1640.53 1746.59,1638.68 1457.88,1638.68 1457.88,1726.72 1467.11,1735.95 1513.28,1735.95
VDD1_3V3 on Top Layer "VDD1_3V3_L01_P45150" (solid, remove dead copper, pour order 45150): 1135.6,1203.94 1135.6,1102.24 1210.86,1102.24 1210.86,1188.98 1189.58,1210.27 1189.58,1292.39 1135.6,1292.39
REG_OUT_1V8 on Top Layer "REG_OUT_1V8_L01_P45218" (solid, remove dead copper, pour order 45218): 1439.09,1177.22 1432.05,1170.19 1432.05,1004.08 1441.81,994.44 1754.23,994.44 1759.41,999.62 1759.41,1072.51 1662.15,1169.77 1553.67,1169.77 1546.21,1177.22
VCC_5V_IN on Top Layer "VCC_5V_IN_L01_P45160" (solid, remove dead copper, pour order 45160): 424.26,1454.95 535.48,1454.95 544.73,1445.7 544.73,1348.82 534.56,1338.65 437.13,1338.65 424.26,1351.52
REG_OUT_3V3 on Top Layer "Top Layer-REG_OUT_3V3" (solid, remove dead copper, pour order 45187): 1151.22,449.07 1147.67,452.62 1147.67,580.64 1221.83,654.79 1221.83,719.14 1241,738.31 1277.31,738.31 1279.31,736.31 1279.31,736.09 1279.31,472.95 1255.43,449.07
REG_1V8 on Top Layer "REG_1V8_L01_P45244" (solid, remove dead copper, pour order 45244): 1222.43,1177.22 1400.56,1177.22 1400.56,1010.96 1222.43,1010.96
USB_5V_D1 on Top Layer "USB_5V_D1_L01_P45217" (solid, pour order 45217): 2521.65,1014.35 2578.22,1014.35 2651.47,1014.35 2681.26,984.57 2704.33,984.57 2713.05,975.85 2713.49,975.85 2713.49,918.09 2521.65,918.09
CONN_5V on Top Layer "CONN_5V_L01_P45162" (solid, remove dead copper, pour order 45162): 413.41,1315.05 611.41,1315.05 640.24,1286.22 640.24,1204.53 619.74,1184.03 413.41,1184.03 414.65,1182.79 413.62,1181.76 305.53,1181.76 289.03,1198.25 289.03,1305.66 301.44,1318.07 301.44,1420.19 413.41,1420.19
VCC_3V3 on Top Layer "VCC_3V3_L01_P45148" (solid, remove dead copper, pour order 45148): 1201.39,1216.4 1201.39,1298.73 1309.53,1298.73 1309.53,1216.4
REG_3V3 on Top Layer "REG_3V3_L01_P45222" (solid, remove dead copper, pour order 45222): 1118.52,343.58 1131.89,356.95 1131.89,521.22 1126.76,526.36 912.35,526.36 912.35,343.58
VCC_MOD_3V3 on Top Layer "VCC_MOD_3V3_L01_P45229" (solid, remove dead copper, pour order 45229): 1547.65,211.56 1834.03,211.56 1849.09,196.5 1849.09,102.17 1795.19,48.26 1570.2,48.26 1546.77,71.7 1547.65,72.59
3V3_MODULE_SNS on Top Layer "3V3_MODULE_SNS_L01_P45237" (solid, pour order 45237): 1542.65,214.79 1542.65,72.59 1180.4,72.59 1156.83,96.17 1156.83,200.57 1171.05,214.79
3V3_IO_SNS on Top Layer "3V3_IO_SNS_L01_P45235" (solid, remove dead copper, pour order 45235): 401.85,216.08 407.58,221.81 865.07,221.81 865.07,94.42 410.1,94.42 401.85,102.67
VCC_IO_3V3 on Top Layer "VCC_IO_3V3_L01_P45230" (solid, remove dead copper, pour order 45230): 872.13,56.13 872.13,223.79 1046.03,223.79 1099.5,170.32 1099.5,87.82 1067.81,56.13
VCC_5V on Top Layer "VCC_5V_L01_P45233" (solid, remove dead copper, pour order 45233): 1965.2,181.92 1974.23,190.95 1974.23,205.04 1985.44,216.25 2032.15,216.25 2047.34,201.06 2047.34,186.61 2052.61,181.92 2121.55,181.92 2159.79,220.16 2159.79,440.88 1808.04,440.88 1808.04,273.63 1899.76,181.92
5V_SNS on Top Layer "5V_SNS_L01_P45232" (solid, remove dead copper, pour order 45232): 2164.79,220.16 2164.79,443.8 2487.3,443.8 2487.3,317.48 2391.68,221.86 2177.74,221.86
FTDI_VBUS on Top Layer "FTDI_VBUS_L01_P45165" (solid, pour order 45165): 2803.36,1335.41 2753.5,1335.41 2744.55,1326.46 2731.04,1326.46 2721.69,1335.87 2641.52,1335.87 2641.52,1273.18 2865.59,1273.18 2898.11,1305.69 2898.11,1319.6 2897.09,1320.95 2817.82,1320.95
GND on Top Layer "GND_L01_P45227" (solid, remove dead copper, pour order 45227): 203.18,1399.3 260.2,1399.3 274.41,1385.09 274.41,1226.13 260.03,1211.75 209.92,1211.75 194.49,1227.19 194.49,1391.49 201.37,1398.37
VCC_MODULE on Top Layer "VCC_MODULE_L01_P45164" (solid, remove dead copper, pour order 45164): 1091.75,3545.3 1299.63,3545.3 1310.52,3534.4 1310.52,3458.17 1297.45,3445.09 1297.24,3445.3 1091.75,3445.3
GND on Top Layer "Top Layer-GND 9" (solid, remove dead copper, pour order 45189): 1412.66,382.74 1414.31,384.39 1414.31,672.24 1420.67,678.29 1420.67,771.86 1436.06,787.26 1436.06,810.8 1431.19,815.67 1407.38,815.67 1407.38,710.46 1397.81,700.89 1374.87,700.89 ccw(c1374.72,684.05) 1362.92,696.06 1354.3,687.44 ccw(c1359.94,681.8) 1351.97,681.79 1351.97,655.03 1291.9,655.02 1291.9,450.06 1284.94,441.8 1194.12,441.8 1194.12,335.56 1365.48,335.56
DC_JACK_5V on Top Layer "DC_JACK_5V_L01_P45166" (solid, pour order 45166): 2626.72,594.52 2626.72,528.68 2705.92,449.48 2705.92,249.09 2515.64,249.09 2515.64,594.52
NetD6_2 on Top Layer "NETD6_2_L01_P45193" (solid, pour order 45193): 1795.75,662.02 2006.72,662.02 2006.72,491.85 1795.75,491.85
GND on L2_GND1 "GND_L02_P45251" (solid, remove dead copper, pour order 45251): 3032.48,3599.79 3032.48,0 -1.01,0 -1.01,3599.79
VCC_3V3 on Bottom Layer "VCC_3V3_L04_P45149" (solid, remove dead copper, pour order 45149): 174.29,1839.86 270.57,1839.86 307.79,1877.08 307.79,2162.51 295.73,2174.56 235.93,2174.56 174.29,2112.92
GND on Bottom Layer "Bottom Layer-GND" (solid, remove dead copper, pour order 45268): 11.34,-12.09 3044.84,-12.09 3044.84,3587.71 3032.48,3587.71 3032.48,3599.79 -1.01,3599.79 -1.01,2740.88 11.34,2740.88
VCC_MOD_3V3 on Bottom Layer "VCC_MOD_3V3_L04_P45172" (solid, remove dead copper, pour order 45172): 1706.7,113.31 1720.62,99.39 1839.85,99.39 1842.22,101.75 1842.22,185.22 1837.62,189.82 1817.62,209.81 1721.62,209.81 1706.7,194.88
3V3_IO_SNS on Bottom Layer "3V3_IO_SNS_L04_P45173" (solid, remove dead copper, pour order 45173): 877.81,202.71 812.66,137.57 606.42,137.57 579.92,111.07 409.98,111.07 397.67,123.37 397.67,218.57 403.4,224.3 632.15,224.3 696.51,224.3 790.31,318.09 871.31,318.09 877.81,311.59
REG_OUT_1V8 on Bottom Layer "REG_OUT_1V8_L04_P45180" (solid, pour order 45180): 1445.37,1034.03 1570.24,1034.03 1582.31,1046.09 1582.31,1120.09 1571.31,1131.09 1439.31,1131.09 1432.31,1124.09 1432.31,1047.09
REG_OUT_3V3 on Bottom Layer "Top Layer-REG_OUT_3V3" (solid, remove dead copper, pour order 45181): 1129.06,594.24 1129.06,608.16 1156.05,635.14 1283.63,635.14 1283.63,475.97 1129.06,475.97
GND on Bottom Layer "GND_L04_P45182" (solid, remove dead copper, pour order 45182): 2403.22,828.32 2393.92,837.62 2393.92,875.14 2357.18,875.14 2357.18,832.89 2345.16,822.09 2169.63,822.09 2160.66,812.76 2160.66,713.73 2181.65,692.74 2493.04,692.74 2493.04,828.32
3V3_MODULE_SNS on Bottom Layer "NONET_L08_P-001" (solid, remove dead copper, pour order 45183): 1114.43,72.59 1114.43,163.87 1059.93,218.37 1045.51,218.37 1029.13,234.75 1029.13,360.86 1110.11,360.86 1116.54,354.43 1116.45,354.33 1116.45,254.93 1115.86,254.35 1115.86,237.57 1138.64,214.79 1299.82,214.79 1299.82,72.59
VCC_3V3 on Bottom Layer "VCC_3V3_L04_P45184" (solid, pour order 45184): 1223.78,238.4 1223.78,322.57 1213.05,333.3 1145.11,333.3 1139.92,328.11 1139.92,245.02 1147.74,237.19 1222.58,237.19
VCC_3V3 on Bottom Layer "VCC_3V3_L04_P45185" (solid, pour order 45185): 681.17,487.67 681.17,403.49 691.9,392.76 759.84,392.76 765.03,397.96 765.03,481.05 757.21,488.87 682.37,488.87
VCC_5V_IN on Bottom Layer "NONET_L08_P-001" (solid, remove dead copper, pour order 45188): 2082.72,1061.05 2096.3,1074.63 2217.08,1074.63 2229.76,1061.94 2229.76,980.16 2229.15,979.55 2228.75,979.95 2082.72,979.95 2082.72,1011.68
5V_SNS on Bottom Layer "NONET_L08_P-001" (solid, remove dead copper, pour order 45216): 2136.51,699.09 2136.51,741.08 2106.84,769.92 2106.84,807.24 2142.86,843.27 2235.18,843.27 2235.18,939.46 2235.27,939.55 2228.84,945.99 2011.14,945.99 1964.71,899.55 1964.71,625.62 2075.33,515 2278.32,515 2331.17,462.16 2331.17,336.81 2498.79,336.81 2498.79,610.07 2440.67,668.2 2167.4,668.2
VCC_3V3 on Bottom Layer "VCC_3V3_L04_P45219" (solid, remove dead copper, pour order 45219): 2359.31,968.09 2324.31,1003.09 2322.31,1003.09 2254.31,1003.09 2241.31,1016.09 2241.31,1111.09 2262.31,1132.09 2616.31,1132.09 2661.31,1087.09 2661.31,978.09 2636.31,953.09 2635.31,954.09 2562.31,954.09 2559.31,957.09 2559.31,1007.09 2562.31,1010.09 2608.31,1010.09 2620.31,1022.09 2620.31,1061.09 2611.31,1070.09 2465.31,1070.09 2461.31,1074.09 2461.31,1101.09 2455.31,1107.09 2411.31,1107.09 2385.31,1081.09 2277.31,1081.09 2270.31,1074.09 2270.31,1043.09 2279.31,1034.09 2346.31,1034.09 2402.31,978.09 2402.31,911.11 2342.51,851.32 2342.51,836.62 2258.65,836.62 2258.65,913.23 2262.91,917.49 2263.51,918.09 2337.31,918.09 2359.31,940.09
REG_3V3 on Bottom Layer "Bottom Layer-REG_3V3" (solid, remove dead copper, pour order 45238): 825.55,356.64 955.05,356.64 1012.82,412.92 1105.48,412.92 1107.43,414.87 1107.43,575.22 1109.31,577.09 1099.31,587.09 1030.64,587.09 1030.64,587.76 919.56,587.76 848.83,587.76 790.46,529.39 790.46,391.72
VCC_3V3 on Bottom Layer "VCC_3V3_L04_P45260" (solid, pour order 45260): 1675.77,501.19 1692.26,501.19 1697.8,506.73 1697.8,577.3 1763.59,577.3 1763.59,470.3 1757.79,464.51 1677.23,464.51 1675.77,465.98
GND on Bottom Layer "GND_L04_P45261" (solid, pour order 45261): 1621.27,403.45 1628.31,410.48 1628.31,566.09 1636.31,574.09 1682.25,574.09 1686.36,570.09 1686.36,521.43 1669.82,504.88 1669.82,437.06 1672.11,434.77 1672.11,434.64 1672.52,434.02 1724.14,434.02 1729.11,429.05 1729.11,401.31 1726.24,398.44 1672.61,398.44 1672.11,397.94 1661.6,387.22 1661.6,345.87 1655.43,339.7 1610.65,339.7 1605.65,344.71 1605.65,387.82
GND on Bottom Layer "GND_L04_P45262" (solid, remove dead copper, pour order 45262): 1312.72,583.89 1404.95,583.89 1417.43,571.42 1417.43,461.96 1369.83,414.37 1298.1,414.37 1298.1,569.66 1312.27,583.83
VCC_5V_IN on Bottom Layer "VCC_5V_IN_L04_P45263" (solid, remove dead copper, pour order 45263): 532.46,819.11 615.6,902.26 615.6,1493.37 443.99,1493.37 426.46,1475.84 426.46,1050.59 289.04,913.17 121.59,913.17 97.53,889.11 97.53,829.3 107.71,819.11
VCC_5V on Bottom Layer "Bottom Layer-VCC_5V" (solid, remove dead copper, pour order 45264): 1438.61,535.47 1462,558.87 1462,682.17 1463.68,683.75 1493.52,683.75 1499.02,689.25 1499.05,690.09 1499.05,745.49 1499.05,855.57 1902.29,855.57 1942.5,815.36 1942.5,604.23 1988.51,558.23 1988.51,311.63 1780.44,311.63 1780.75,344.8 1780.75,579.65 1765.31,595.09 1632.96,595.09 1619.31,581.22 1619.31,468.09 1618.31,467.09 1438.61,467.09
VCC_IO_3V3 on Bottom Layer "VCC_IO_3V3_L04_P45179" (solid, remove dead copper, pour order 45179): 954.31,108.09 962.52,99.88 1081.75,99.88 1084.11,102.25 1084.11,185.71 1079.51,190.31 1059.52,210.31 963.52,210.31 954.31,201.09
GND on L3_PWR1 "GND_L03_P45269" (solid, remove dead copper, pour order 45269): 3032.48,3599.79 3032.48,0 -1.01,0 -1.01,3599.79
GND on L3_PWR1 "GND_L03_P45205" (solid, remove dead copper, pour order 45205): 657.14,2857.08 651.67,2851.62 651.67,2723.94 803.72,2571.35 803.72,2233.27 902.98,2233.27 902.98,2459.39 999.22,2555.63 999.22,2825.25 967.39,2857.08
VCC_3V3 on L3_PWR1 "ga" (solid, remove dead copper, pour order 45267): 243.16,1822.01 272.86,1851.71 272.86,2595.2 386.75,2709.09 415.88,2709.09 498.42,2626.56 498.42,2407.51 500.05,2405.88 500.05,2405.27 612.72,2292.6 639.16,2266.91 639.16,2149.18 655.91,2132.43 713.47,2132.43 751.15,2170.1 751.15,2185.93 790.31,2225.09 1026.31,2225.09 1032.31,2231.09 1032.31,2352.09 1233.31,2553.09 1491.31,2553.09 1531.31,2593.09 1669.31,2593.09 1688.31,2612.09 1688.31,2646.09 1677.31,2657.09 1350.31,2657.09 1318.01,2686.86 1312.93,2691.95 1313.66,2740.83 1403.92,2831.83 2846.16,2831.83 2846.16,1098.4 1979.47,231.71 337.69,231.71 243.16,326.24
REG_1V8 on L3_PWR1 "REG_1V8_L03_P45214" (solid, remove dead copper, pour order 45214): 2284.23,2785.09 2074.23,2995.09 1893.1,2995.09 1760.91,3127.28 1105.04,3127.28 1087.6,3144.72 532.94,3144.72 505.61,3117.39 505.61,2420.79 598.29,2328.11 598.29,1873.11 877.9,1593.5 877.9,1472.15 981.28,1368.76 1102.06,1369.34 1153.31,1318.09 1153.31,1037.1 1215.77,974.64 1362.41,974.64 1362.41,976.09 1428.17,1042.96 1428.17,1272.23 1127.2,1573.2 1127.2,1675.75 877.86,1925.09 877.86,2059.77 812.7,2124.93 812.7,2223.31 794.46,2241.55 794.46,2554.94 632.31,2717.09 632.31,2851.06 663.29,2882.05 975.57,2882.05 1011.31,2845.09 1011.31,2661.09 1069.31,2603.09 1656.8,2603.09 1754.07,2701.24 2061.18,2701.24 2191.19,2571.24 2419.04,2571.24 2419.04,2732.48 2366.43,2785.09
GND on L3_PWR1 "GND_L03_P45201" (solid, remove dead copper, pour order 45201): 1095.31,1370.09 946.31,1370.09 850.51,1465.89 850.51,1540.4 830.09,1559.07 765.44,1559.07 765.44,1226.01 737.7,1198.26 737.7,1139.14 754.33,1122.5 1062.54,1122.5 1095.31,1155.27
VCC_XDS_3V3 on L3_PWR1 "VCC_XDS_3V3_L03_P45248" (solid, remove dead copper, pour order 45248): 1253.84,2031.9 1312.29,1973.45 1576.53,1973.45 1904.14,2301.07 1979.25,2301.07 2023.16,2343.27 2023.51,2343.62 2120.39,2343.62 2120.39,2421.85 2087.54,2456.14 2006.16,2456.14 1960.09,2502.21 1960.09,2569.7 1930.52,2599.28 1862.35,2599.28 1820.94,2557.87 1820.94,2509.84 1726.47,2415.36 1484.85,2415.36 1253.84,2183.46
GND on L3_PWR1 "GND_L03_P45200" (solid, remove dead copper, pour order 45200): 767.38,2140.7 833.5,2140.7 917.75,2056.45 917.75,1898.23 897.28,1877.76 864.15,1877.76 766.19,1975.71 766.19,2138.41
VCC_MOD_3V3 on L3_PWR1 "VCC_MOD_3V3_L03_P45220" (solid, remove dead copper, pour order 45220): 2275.14,2130.27 2748.31,2130.27 2748.62,2418.78 2823.62,2493.78 2893.92,2493.78 2905.6,2505.46 2905.6,2576.27 2894.17,2587.67 2770.11,2587.67 2639.69,2718.09 2532.31,2718.09 2443.65,2629.44 2443.65,2603.4 2382.1,2541.86 2306.55,2541.86 2269.62,2504.93 2269.62,2347.75 2260.16,2339.47 1973.03,2339.47 1637.11,2003.55 1637.11,1702.57 1919.3,1420.37 1919.3,1135.9 1984.72,1070.48 2150.92,1070.48 2185.95,1035.45 2185.95,991.74 2333.12,846.65 2333.12,705.68 2089.68,462.24 1964.45,462.24 1707.33,205.12 1707.33,134.04 1722.28,119.09 2095.88,119.09 2605.31,628.52 2605.31,1035.34 2473.25,1167.41 2288.06,1167.41 2122.61,1332.85 2122.61,1449.57 2258.94,1584.5 2258.94,1713.71 2156.4,1816.24 1975.56,1816.24 1929.44,1862.36 1929.44,2007.57 2030.71,2108.84 2253.72,2108.84
GND on L3_PWR1 "GND_L03_P45239" (solid, remove dead copper, pour order 45239): 2695.14,930.77 2668.46,904.09 2614.31,904.09 2614.31,605.09 2509.31,500.09 2510.31,499.09 2510.31,368.09 2629.31,249.09 2881.31,249.09 2912.31,280.09 2912.31,554.09 2877.31,589.09 2877.31,901.42 2878.17,902.28 2878.17,992.95 2883.31,998.09 2883.31,1467.96 2571.95,1779.31 2526.13,1779.32 2371.82,1779.32 2322.26,1828.88 2322.26,1944.37 2304.01,1962.62 2254.74,1962.62 2236.9,1980.46 2236.9,2072.22 2215.57,2093.55 2125.96,2093.55 2094.08,2061.66 2004.96,2061.66 1951.04,2007.74 1951.04,1840.76 2161.42,1840.76 2236.9,1765.28 2236.9,1539.97 2161.42,1464.49 2161.42,1304.89 2243.21,1223.09 2637.33,1223.09 2695.14,1165.29
VCC_MODULE on L3_PWR1 "VCC_MODULE_L03_P45249" (solid, remove dead copper, pour order 45249): 2025.29,3229.11 2144.8,3109.6 2144.8,2932.81 2349.98,2727.63 2646.09,2727.63 2762.94,2610.79 2762.94,2234.88 3005.36,2234.88 3005.36,3251.04 2738.71,3517.69 2727.99,3528.64 2197.2,3528.64 2163.62,3562.21 1116.81,3562.21 1088.98,3534.38 1088.98,3313.1 1172.97,3229.11
VCC_5V_IN on L3_PWR1 "VCC_5V_IN_L03_P45247" (solid, remove dead copper, pour order 45247): 647.01,1485.39 674.31,1458.09 674.31,1262.09 647.01,1234.99 647.01,1102.39 856.83,892.57 1925.35,892.57 2076.48,1059.36 2140.52,1059.36 2168.89,1030.98 2168.89,850.9 1945.83,627.85 615.55,627.85 458.26,785.14 458.26,1457.63 486.02,1485.39

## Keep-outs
Keep-Out Layer:
  circle w10: c224.34,3464 r90
  circle w10: c2807.13,3454.52 r90
  circle w10: c2806.34,3068.7 r90
  circle w10: c2807.13,3454.52 r137.79
  circle w10: c2806.34,3068.7 r137.79
  circle w10: c225.13,106.94 r137.79
  circle w10: c2465.13,106.94 r137.79
  circle w10: c224.34,3464 r137.79
  circle w1: c586.63,524.74 r32
  circle w1: c586.63,1317.26 r32
  text ".Layer_Name" at -497.74,-628.87 h60

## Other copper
Top Layer:
  region net SW3: 1708.38,879.53 ccw(c1710.33,879.53) 1710.33,877.58 1718.99,877.58 ccw(c1718.99,879.5) 1720.92,879.5 1720.92,906.01 cw(c1748.85,906.01) 1729.1,925.77 1733.73,930.4 cw(c1742.47,921.67) 1742.47,934.02 ccw(c1742.47,936.27) 1744.06,934.68 1744.9,935.52 ccw(c1743.4,937.02) 1745.52,937.02 1745.52,960.1 ccw(c1733.83,960.1) 1742.1,968.36 1682.77,968.36 1678.24,963.83 1678.24,938.15 1680.52,934.22 1681.35,933.36 1684.91,931.89 1686.79,931.5 1687.71,931.34 1689.05,930.82 1690.25,930.04 1690.79,929.57 1706.01,914.36 cw(c1700.3,908.64) 1708.38,908.64
  region net SW1: 1363.75,722.01 cw(c1363.75,734.9) 1354.64,725.79 1342.12,738.3 1337.49,739.02 1311.21,739.02 1307.41,735.23 1307.41,684.09 1311.94,679.56 1337.62,679.56 1341.56,681.84 1342.42,682.67 1343.89,686.23 1344.28,688.11 1344.44,689.03 1344.96,690.37 1345.73,691.57 1346.2,692.11 1361.42,707.33 1362.25,708.08 1364.11,709.33 1366.18,710.18 1368.38,710.62 1369.5,710.68 1392.69,710.68 1397.36,710.68 1397.84,711.29 1397.94,717.98 1397.9,718.02 1397.98,720.21 1396.17,722.01
  region net 5V_JACK_IN: 1944.62,887.81 1948.7,883.73 1999.61,883.73 2001.2,882.14 2005.23,878.11 ccw(c2009.4,882.09) 2009.27,876.33 2009.38,876.32 2044.52,876.32 2057.57,863.14 2057.96,861.11 ccw(c2068.15,871.33) 2068.17,856.9 2091.32,856.9 cw(c2091.33,854.89) 2092.75,856.31 2093.12,855.94 cw(c2091.85,854.65) 2093.66,854.64 2093.65,854.37 2093.69,844.19 2057.98,844.19 2041.28,860.9 2040.63,861.87 2039.65,862.52 2038.92,863.25 2038.56,863.25 2037.34,864.07 2035.11,864.51 2009.32,864.51 2007.09,864.07 2003.8,861.87 2001.6,858.58 2001.52,858.19 1996.4,853.07 1995.65,852.24 1994.41,850.37 1993.55,848.3 1993.11,846.11 1993.06,844.99 1993.06,700.03 1793.37,700.03 1793.37,785.13 1896.05,887.8
  region net VCC_5V_IN: 2061.46,884.59 2061.99,884.06 2090.59,884.06 ccw(c2090.59,886.64) 2092.41,884.81 2093.05,885.45 ccw(c2091.55,886.98) 2093.69,886.97 2093.69,893.12 2093.69,894.24 ccw(c2092.18,894.24) 2093.24,895.31 2092.53,896.03 ccw(c2091.35,894.85) 2091.35,896.51 2091.3,896.52 2090.18,896.52 2065.46,896.45 2065.36,896.47 2062.07,898.66 2059.87,901.96 2059.1,905.84 2059.1,913.75 2059.87,917.63 2061.57,920.17 2061.57,922.68 2061.63,924.05 2062.17,926.73 2063.21,929.25 2064.73,931.52 2065.65,932.54 2066.4,933.22 2068.09,934.35 2069.97,935.13 2071.96,935.52 2072.98,935.57 2096.86,935.57 2098.44,935.62 2101.52,936.34 2104.4,937.64 2106.97,939.47 2108.06,940.62 2117.59,950.16 2156.77,950.16 2173.02,966.42 2173.02,1064.59 2034.74,1064.59 2034.74,939.61 2034.74,938.98 2036.73,934.81 2038.71,932.82 2039.61,931.83 2040.04,931.18 2041.09,929.62 2041.85,927.79 2042.11,927.16 2042.63,924.55 2042.69,923.22 2042.69,917.83 2042.82,917.63 2043.6,913.75 2043.6,905.84 2042.82,901.96 2040.63,898.66 2037.34,896.47 2033.45,895.69 2010.97,895.69 2008.52,893.68 2008.52,888.87 2008.83,888.16 2010.97,884.52 2033.45,884.52 2033.95,884.43 2034,884.43 2034.8,884.43 2035.59,884.59
  region net 5V_IN_USB: 2091.26,876.02 2096.08,876.02 2103.99,883.94 2103.99,892.11 cw(c2109.6,892.43) 2105.41,896.17 2106.87,897.63 cw(c2112.51,891.92) 2112.57,899.94 2127.15,899.94 2175.49,899.94 2245.93,970.37 2245.93,1155.36 2246.74,1155.36 2335.99,1244.61 2487.5,1244.61 2511.06,1268.17 2604.15,1268.17 2622.91,1249.42 2622.91,1117.55 2607.72,1102.37 2606.75,1103.34 2363.45,1103.34 2341.31,1081.2 2341.31,917.62 2266.54,842.86 2119.37,842.86 2119.35,842.87 2112.06,842.87 2110.7,842.92 cw(c2110.7,846.17) 2108.4,843.88 2104.32,847.92 2103.77,848.51 cw(c2106.75,851.49) 2102.54,851.49 2102.54,857.5 ccw(c2100.41,857.49) 2101.9,859.01 2097.21,863.7 ccw(c2095.29,861.78) 2095.28,864.5 2090.25,864.5 2069.56,864.5 cw(c2069.56,866.17) 2068.38,864.99 2067.99,865.38 cw(c2069.07,866.52) 2067.49,866.47 2067.49,875.44 2068.08,876.02 2068.11,876.02 2088.76,876.02 ccw(c2088.76,898.39) 2088.89,876.02 2090.1,876.02
  region net VCC_5V: 1634.31,839.09 1683.62,839.09 1690.39,845.87 1718.8,845.87 1720.75,843.92 1720.75,793.02 1712.42,784.69 1498.71,784.69 1485.31,798.09 1485.31,830.23 1494.17,839.09
  text ".Layer_Name" at -378.69,-674.91 h60
L2_GND1:
  pour cut-out: 16.02,2080.86 78.23,2080.86 121.15,2037.95 251.13,2037.95 260.98,2028.1 260.98,1964.56 250.08,1953.66 121.78,1953.66 78.56,1910.44 18.15,1910.44 15.02,1913.58 15.02,2079.86
  text ".Layer_Name" at -547.83,-673.82 h60
L3_PWR1:
  text ".Layer_Name" at -544.88,-674.55 h60
Bottom Layer:
  text ".Layer_Name" at -378.69,-674.91 h60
